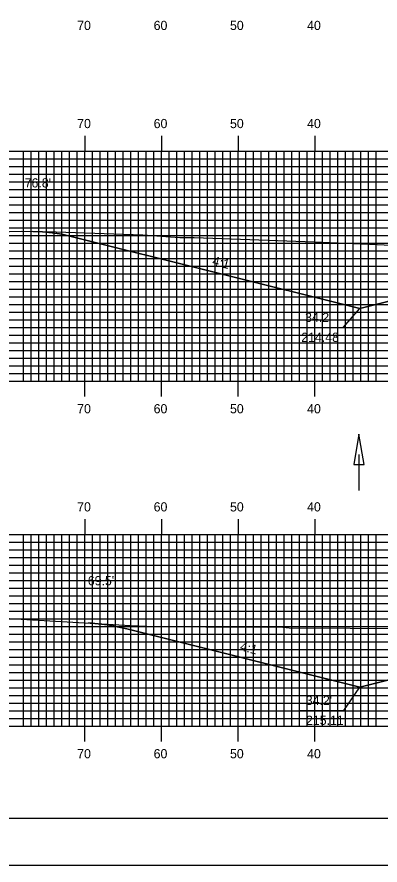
# Model space of a CAD drawing. Extents: x 1820424 to 1820768, y 442591 to 442811.
# Drawn here: x 1820511.4 to 1820558.7, y 442590.5 to 442701.2 of the extents above; entities that cross this region are included whole.
import ezdxf

# ---------------------------------------------------------------- set-up
doc = ezdxf.new("R2010")
doc.units = 0
for name, color, linetype in [('ANNOTATION', 7, 'Continuous'), ('BORDER', 7, 'Continuous'), ('D_Drainage_Ditch_Line', 7, 'Continuous'), ('D_Roadway_Centerline', 7, 'Continuous'), ('D_Roadway_SlopeLines', 7, 'Continuous'), ('D_Text_Standard', 7, 'Continuous'), ('H_V ANNOTATION', 7, 'Continuous'), ('MAJOR', 7, 'Continuous'), ('MINOR', 7, 'Continuous'), ('PLOT BOUNDARY', 7, 'Continuous'), ('S_Roadway_Centerline', 7, 'Continuous')]:
    doc.layers.add(name, color=color, linetype=linetype)

msp = doc.modelspace()

# ---------------------------------------------------------------- linework, layer by layer
at = {"layer": 'ANNOTATION'}
for points in [[(1820548.19, 442660.66), (1820553.88, 442660.66), (1820556.03, 442663.15)], [(1820548.27, 442610.7), (1820553.97, 442610.7), (1820556.03, 442613.77)]]:
    msp.add_lwpolyline(points, dxfattribs=at)
at = {"layer": 'BORDER'}
msp.add_lwpolyline([(1820440.6, 442596.67), (1820760.6, 442596.67), (1820760.6, 442806.67), (1820440.6, 442806.67)], close=True, dxfattribs=at)
at = {"layer": 'D_Drainage_Ditch_Line'}
msp.add_line((1820555.94, 442644.11), (1820555.94, 442639.41), dxfattribs=at)
msp.add_lwpolyline([(1820555.28, 442642.79), (1820556.6, 442642.79), (1820555.94, 442646.73)], close=True, dxfattribs=at)
at = {"layer": 'D_Roadway_Centerline'}
for points in [[(1820513.44, 442673.2), (1820514.69, 442673.15), (1820515.94, 442673.02), (1820517.19, 442672.82), (1820518.44, 442672.55), (1820556.03, 442663.15), (1820560.03, 442664.15), (1820570.2, 442666.69), (1820578.2, 442667.01), (1820590.2, 442667.25), (1820602.2, 442667.01), (1820612.2, 442666.61), (1820622.2, 442664.11), (1820626.2, 442663.11), (1820646.94, 442668.3), (1820648.19, 442668.56), (1820649.44, 442668.74), (1820650.69, 442668.83), (1820651.94, 442668.83)], [(1820520.69, 442622.13), (1820521.94, 442622.03), (1820523.19, 442621.86), (1820524.44, 442621.64), (1820525.69, 442621.36), (1820556.03, 442613.77), (1820560.03, 442614.77), (1820570.2, 442617.32), (1820578.2, 442617.64), (1820590.2, 442617.88), (1820602.2, 442617.64), (1820612.2, 442617.24), (1820622.2, 442614.74), (1820626.2, 442613.74), (1820645.7, 442618.61), (1820646.95, 442618.88), (1820648.2, 442619.06), (1820649.45, 442619.15), (1820650.7, 442619.16)]]:
    msp.add_lwpolyline(points, dxfattribs=at)
at = {"layer": 'D_Roadway_SlopeLines'}
for points in [[(1820556.03, 442663.15), (1820518.44, 442672.55), (1820517.19, 442672.82), (1820515.94, 442673.02), (1820514.69, 442673.15), (1820513.44, 442673.2)], [(1820570.2, 442666.69), (1820556.03, 442663.15)], [(1820556.03, 442613.77), (1820525.69, 442621.36), (1820524.44, 442621.64), (1820523.19, 442621.86), (1820521.94, 442622.03), (1820520.69, 442622.13)], [(1820570.2, 442617.32), (1820556.03, 442613.77)]]:
    msp.add_lwpolyline(points, dxfattribs=at)
at = {"layer": 'MAJOR'}
for p, q in [((1820520.2, 442685.67), (1820520.2, 442683.67)), ((1820530.2, 442685.67), (1820530.2, 442683.67)), ((1820540.2, 442685.67), (1820540.2, 442683.67)), ((1820550.2, 442685.67), (1820550.2, 442683.67)), ((1820450.2, 442683.67), (1820730.2, 442683.67)), ((1820450.2, 442683.67), (1820730.2, 442683.67)), ((1820520.2, 442653.67), (1820520.2, 442683.67)), ((1820530.2, 442653.67), (1820530.2, 442683.67)), ((1820540.2, 442653.67), (1820540.2, 442683.67)), ((1820550.2, 442653.67), (1820550.2, 442683.67)), ((1820450.2, 442678.67), (1820730.2, 442678.67)), ((1820450.2, 442673.67), (1820730.2, 442673.67)), ((1820450.2, 442668.67), (1820730.2, 442668.67)), ((1820450.2, 442663.67), (1820730.2, 442663.67)), ((1820450.2, 442658.67), (1820730.2, 442658.67)), ((1820450.2, 442653.67), (1820730.2, 442653.67)), ((1820450.2, 442653.67), (1820730.2, 442653.67)), ((1820520.2, 442651.66), (1820520.2, 442653.67)), ((1820530.2, 442651.66), (1820530.2, 442653.67)), ((1820540.2, 442651.66), (1820540.2, 442653.67)), ((1820550.2, 442651.66), (1820550.2, 442653.67)), ((1820520.2, 442635.67), (1820520.2, 442633.67)), ((1820530.2, 442635.67), (1820530.2, 442633.67)), ((1820540.2, 442635.67), (1820540.2, 442633.67)), ((1820550.2, 442635.67), (1820550.2, 442633.67)), ((1820450.2, 442633.67), (1820730.2, 442633.67)), ((1820450.2, 442633.67), (1820730.2, 442633.67)), ((1820520.2, 442608.67), (1820520.2, 442633.67)), ((1820530.2, 442608.67), (1820530.2, 442633.67)), ((1820540.2, 442608.67), (1820540.2, 442633.67)), ((1820550.2, 442608.67), (1820550.2, 442633.67)), ((1820450.2, 442628.67), (1820730.2, 442628.67)), ((1820450.2, 442623.67), (1820730.2, 442623.67)), ((1820450.2, 442618.67), (1820730.2, 442618.67)), ((1820450.2, 442613.67), (1820730.2, 442613.67)), ((1820450.2, 442608.67), (1820730.2, 442608.67)), ((1820450.2, 442608.67), (1820730.2, 442608.67)), ((1820520.2, 442606.66), (1820520.2, 442608.67)), ((1820530.2, 442606.66), (1820530.2, 442608.67)), ((1820540.2, 442606.66), (1820540.2, 442608.67)), ((1820550.2, 442606.66), (1820550.2, 442608.67))]:
    msp.add_line(p, q, dxfattribs=at)
at = {"layer": 'MINOR'}
for p, q in [((1820512.2, 442653.67), (1820512.2, 442683.67)), ((1820513.2, 442653.67), (1820513.2, 442683.67)), ((1820514.2, 442653.67), (1820514.2, 442683.67)), ((1820515.2, 442653.67), (1820515.2, 442683.67)), ((1820516.2, 442653.67), (1820516.2, 442683.67)), ((1820517.2, 442653.67), (1820517.2, 442683.67)), ((1820518.2, 442653.67), (1820518.2, 442683.67)), ((1820519.2, 442653.67), (1820519.2, 442683.67)), ((1820521.2, 442653.67), (1820521.2, 442683.67)), ((1820522.2, 442653.67), (1820522.2, 442683.67)), ((1820523.2, 442653.67), (1820523.2, 442683.67)), ((1820524.2, 442653.67), (1820524.2, 442683.67)), ((1820525.2, 442653.67), (1820525.2, 442683.67)), ((1820526.2, 442653.67), (1820526.2, 442683.67)), ((1820527.2, 442653.67), (1820527.2, 442683.67)), ((1820528.2, 442653.67), (1820528.2, 442683.67)), ((1820529.2, 442653.67), (1820529.2, 442683.67)), ((1820531.2, 442653.67), (1820531.2, 442683.67)), ((1820532.2, 442653.67), (1820532.2, 442683.67)), ((1820533.2, 442653.67), (1820533.2, 442683.67)), ((1820534.2, 442653.67), (1820534.2, 442683.67)), ((1820535.2, 442653.67), (1820535.2, 442683.67)), ((1820536.2, 442653.67), (1820536.2, 442683.67)), ((1820537.2, 442653.67), (1820537.2, 442683.67)), ((1820538.2, 442653.67), (1820538.2, 442683.67)), ((1820539.2, 442653.67), (1820539.2, 442683.67)), ((1820541.2, 442653.67), (1820541.2, 442683.67)), ((1820542.2, 442653.67), (1820542.2, 442683.67)), ((1820543.2, 442653.67), (1820543.2, 442683.67)), ((1820544.2, 442653.67), (1820544.2, 442683.67)), ((1820545.2, 442653.67), (1820545.2, 442683.67)), ((1820546.2, 442653.67), (1820546.2, 442683.67)), ((1820547.2, 442653.67), (1820547.2, 442683.67)), ((1820548.2, 442653.67), (1820548.2, 442683.67)), ((1820549.2, 442653.67), (1820549.2, 442683.67)), ((1820551.2, 442653.67), (1820551.2, 442683.67)), ((1820552.2, 442653.67), (1820552.2, 442683.67)), ((1820553.2, 442653.67), (1820553.2, 442683.67)), ((1820554.2, 442653.67), (1820554.2, 442683.67)), ((1820555.2, 442653.67), (1820555.2, 442683.67)), ((1820556.2, 442653.67), (1820556.2, 442683.67)), ((1820557.2, 442653.67), (1820557.2, 442683.67)), ((1820558.2, 442653.67), (1820558.2, 442683.67)), ((1820450.2, 442682.67), (1820730.2, 442682.67)), ((1820450.2, 442681.67), (1820730.2, 442681.67)), ((1820450.2, 442680.67), (1820730.2, 442680.67)), ((1820450.2, 442679.67), (1820730.2, 442679.67)), ((1820450.2, 442677.67), (1820730.2, 442677.67)), ((1820450.2, 442676.67), (1820730.2, 442676.67)), ((1820450.2, 442675.67), (1820730.2, 442675.67)), ((1820450.2, 442674.67), (1820730.2, 442674.67)), ((1820450.2, 442672.67), (1820730.2, 442672.67)), ((1820450.2, 442671.67), (1820730.2, 442671.67)), ((1820450.2, 442670.67), (1820730.2, 442670.67)), ((1820450.2, 442669.67), (1820730.2, 442669.67)), ((1820450.2, 442667.67), (1820730.2, 442667.67)), ((1820450.2, 442666.67), (1820730.2, 442666.67)), ((1820450.2, 442665.67), (1820730.2, 442665.67)), ((1820450.2, 442664.67), (1820730.2, 442664.67)), ((1820450.2, 442662.67), (1820730.2, 442662.67)), ((1820450.2, 442661.67), (1820730.2, 442661.67)), ((1820450.2, 442660.67), (1820730.2, 442660.67)), ((1820450.2, 442659.67), (1820730.2, 442659.67)), ((1820450.2, 442657.67), (1820730.2, 442657.67)), ((1820450.2, 442656.67), (1820730.2, 442656.67)), ((1820450.2, 442655.67), (1820730.2, 442655.67)), ((1820450.2, 442654.67), (1820730.2, 442654.67)), ((1820512.2, 442608.67), (1820512.2, 442633.67)), ((1820513.2, 442608.67), (1820513.2, 442633.67)), ((1820514.2, 442608.67), (1820514.2, 442633.67)), ((1820515.2, 442608.67), (1820515.2, 442633.67)), ((1820516.2, 442608.67), (1820516.2, 442633.67)), ((1820517.2, 442608.67), (1820517.2, 442633.67)), ((1820518.2, 442608.67), (1820518.2, 442633.67)), ((1820519.2, 442608.67), (1820519.2, 442633.67)), ((1820521.2, 442608.67), (1820521.2, 442633.67)), ((1820522.2, 442608.67), (1820522.2, 442633.67)), ((1820523.2, 442608.67), (1820523.2, 442633.67)), ((1820524.2, 442608.67), (1820524.2, 442633.67)), ((1820525.2, 442608.67), (1820525.2, 442633.67)), ((1820526.2, 442608.67), (1820526.2, 442633.67)), ((1820527.2, 442608.67), (1820527.2, 442633.67)), ((1820528.2, 442608.67), (1820528.2, 442633.67)), ((1820529.2, 442608.67), (1820529.2, 442633.67)), ((1820531.2, 442608.67), (1820531.2, 442633.67)), ((1820532.2, 442608.67), (1820532.2, 442633.67)), ((1820533.2, 442608.67), (1820533.2, 442633.67)), ((1820534.2, 442608.67), (1820534.2, 442633.67)), ((1820535.2, 442608.67), (1820535.2, 442633.67)), ((1820536.2, 442608.67), (1820536.2, 442633.67)), ((1820537.2, 442608.67), (1820537.2, 442633.67)), ((1820538.2, 442608.67), (1820538.2, 442633.67)), ((1820539.2, 442608.67), (1820539.2, 442633.67)), ((1820541.2, 442608.67), (1820541.2, 442633.67)), ((1820542.2, 442608.67), (1820542.2, 442633.67)), ((1820543.2, 442608.67), (1820543.2, 442633.67)), ((1820544.2, 442608.67), (1820544.2, 442633.67)), ((1820545.2, 442608.67), (1820545.2, 442633.67)), ((1820546.2, 442608.67), (1820546.2, 442633.67)), ((1820547.2, 442608.67), (1820547.2, 442633.67)), ((1820548.2, 442608.67), (1820548.2, 442633.67)), ((1820549.2, 442608.67), (1820549.2, 442633.67)), ((1820551.2, 442608.67), (1820551.2, 442633.67)), ((1820552.2, 442608.67), (1820552.2, 442633.67)), ((1820553.2, 442608.67), (1820553.2, 442633.67)), ((1820554.2, 442608.67), (1820554.2, 442633.67)), ((1820555.2, 442608.67), (1820555.2, 442633.67)), ((1820556.2, 442608.67), (1820556.2, 442633.67)), ((1820557.2, 442608.67), (1820557.2, 442633.67)), ((1820558.2, 442608.67), (1820558.2, 442633.67)), ((1820450.2, 442632.67), (1820730.2, 442632.67)), ((1820450.2, 442631.67), (1820730.2, 442631.67)), ((1820450.2, 442630.67), (1820730.2, 442630.67)), ((1820450.2, 442629.67), (1820730.2, 442629.67)), ((1820450.2, 442627.67), (1820730.2, 442627.67)), ((1820450.2, 442626.67), (1820730.2, 442626.67)), ((1820450.2, 442625.67), (1820730.2, 442625.67)), ((1820450.2, 442624.67), (1820730.2, 442624.67)), ((1820450.2, 442622.67), (1820730.2, 442622.67)), ((1820450.2, 442621.67), (1820730.2, 442621.67)), ((1820450.2, 442620.67), (1820730.2, 442620.67)), ((1820450.2, 442619.67), (1820730.2, 442619.67)), ((1820450.2, 442617.67), (1820730.2, 442617.67)), ((1820450.2, 442616.67), (1820730.2, 442616.67)), ((1820450.2, 442615.67), (1820730.2, 442615.67)), ((1820450.2, 442614.67), (1820730.2, 442614.67)), ((1820450.2, 442612.67), (1820730.2, 442612.67)), ((1820450.2, 442611.67), (1820730.2, 442611.67)), ((1820450.2, 442610.67), (1820730.2, 442610.67)), ((1820450.2, 442609.67), (1820730.2, 442609.67))]:
    msp.add_line(p, q, dxfattribs=at)
at = {"layer": 'PLOT BOUNDARY'}
msp.add_lwpolyline([(1820424.42, 442590.55), (1820764.42, 442590.55), (1820764.42, 442810.55), (1820424.42, 442810.55)], close=True, dxfattribs=at)
at = {"layer": 'S_Roadway_Centerline'}
for points in [[(1820498.3, 442672.85), (1820511.91, 442673.22), (1820516.46, 442673.16), (1820527.78, 442672.74), (1820532.58, 442672.4), (1820534.44, 442672.4), (1820550.15, 442671.85), (1820558.33, 442671.49), (1820567.36, 442671.06), (1820579.85, 442671.62), (1820582.62, 442671.68), (1820584.38, 442671.72), (1820598.43, 442670.57), (1820601.19, 442670.34), (1820601.51, 442670.34), (1820612.27, 442670.48), (1820617.29, 442670.12), (1820624.98, 442669.74), (1820633.74, 442669.3), (1820647.6, 442668.99), (1820651.41, 442668.85)], [(1820497.56, 442623.45), (1820526.17, 442621.81), (1820528.29, 442621.72), (1820535.96, 442621.62), (1820544.01, 442621.59), (1820545.64, 442621.62), (1820546.86, 442621.5), (1820562.73, 442621.39), (1820574.51, 442621.05), (1820580.16, 442620.79), (1820583.51, 442620.76), (1820595.78, 442620.47), (1820597.09, 442620.45), (1820597.94, 442620.43), (1820614.12, 442619.72), (1820619, 442619.45), (1820630.75, 442619.31), (1820640.71, 442619.43), (1820647.54, 442619.26), (1820651.3, 442619.14)]]:
    msp.add_lwpolyline(points, dxfattribs=at)

# ---------------------------------------------------------------- texts
at = {"layer": 'ANNOTATION'}
for p in [(1820536.74, 442668.83), (1820540.36, 442618.55)]:
    msp.add_text('4:1', height=1.2, rotation=345.9638, dxfattribs=at).set_placement(p)
for s, p in [("34.2'", (1820548.92, 442661.39)), ('214.48', (1820548.42, 442658.79)), ("34.2'", (1820549.01, 442611.43)), ('215.11', (1820549.04, 442608.83))]:
    msp.add_text(s, height=1.2, dxfattribs=at).set_placement(p)
at = {"layer": 'D_Text_Standard'}
for s, p in [("76.8'", (1820512.37, 442678.93)), ("69.5'", (1820520.6, 442627.04))]:
    msp.add_text(s, height=1.2, dxfattribs=at).set_placement(p)
at = {"layer": 'H_V ANNOTATION'}
for s, p in [('70', (1820519.21, 442699.47)), ('60', (1820529.18, 442699.47)), ('50', (1820539.13, 442699.47)), ('40', (1820549.18, 442699.47)), ('70', (1820519.21, 442686.67)), ('60', (1820529.18, 442686.67)), ('50', (1820539.13, 442686.67)), ('40', (1820549.18, 442686.67)), ('70', (1820519.21, 442649.47)), ('60', (1820529.18, 442649.47)), ('50', (1820539.13, 442649.47)), ('40', (1820549.18, 442649.47)), ('70', (1820519.21, 442636.67)), ('60', (1820529.18, 442636.67)), ('50', (1820539.13, 442636.67)), ('40', (1820549.18, 442636.67)), ('70', (1820519.21, 442604.47)), ('60', (1820529.18, 442604.47)), ('50', (1820539.13, 442604.47)), ('40', (1820549.18, 442604.47))]:
    msp.add_text(s, height=1.2, dxfattribs=at).set_placement(p)

doc.saveas('drawing.dxf')
